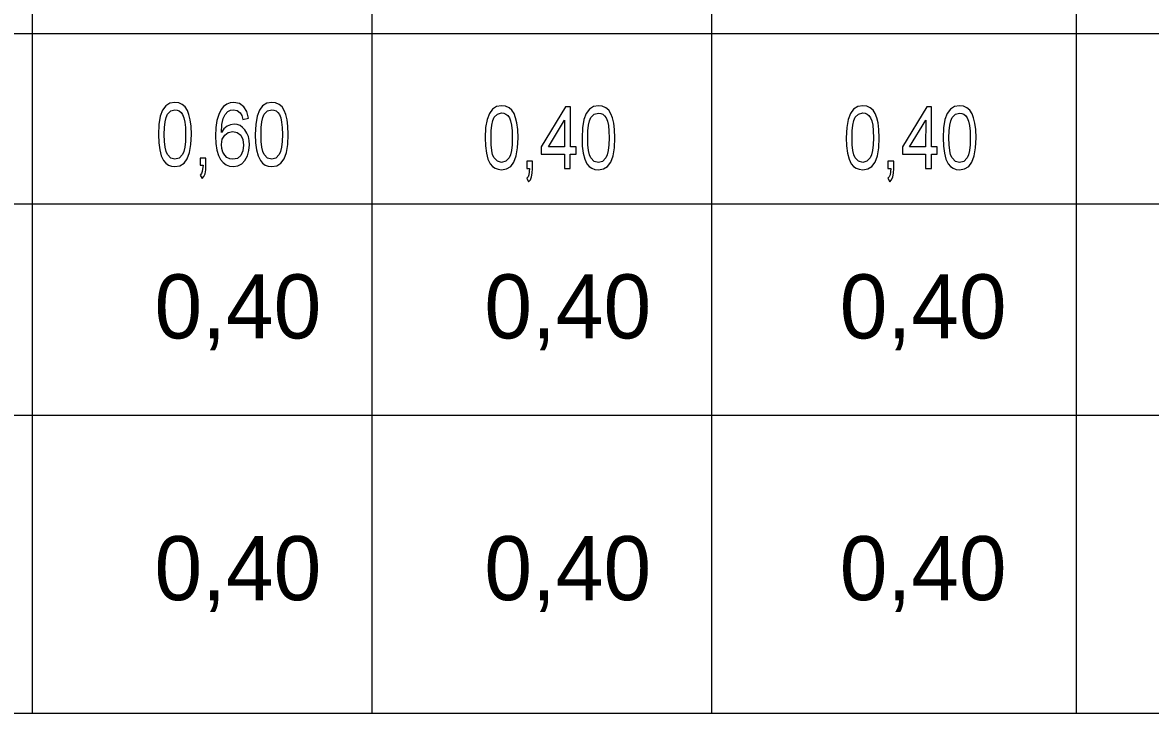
# Model space of a CAD drawing. Extents: x -480568.5 to -480543.1, y -1126945.4 to -1126930.6.
# Drawn here: x -480546.724 to -480545.02, y -1126939.812 to -1126938.768 of the extents above; entities that cross this region are included whole.
import ezdxf

# ---------------------------------------------------------------- set-up
doc = ezdxf.new("R2010")
doc.units = 0
doc.layers.add('detaily', color=7, linetype='Continuous')
doc.layers.add('EL1', color=7, linetype='Continuous')

msp = doc.modelspace()

# ---------------------------------------------------------------- linework, layer by layer
at = {"layer": 'detaily'}
msp.add_lwpolyline([(-480543.5956, -1126939.8124), (-480551.8459, -1126939.8124), (-480551.8459, -1126936.5789), (-480543.5956, -1126936.5789)], close=True, dxfattribs=at)
at = {"layer": 'EL1'}
for p, q in [((-480546.1966, -1126936.5789), (-480546.1966, -1126939.8121)), ((-480545.1324, -1126936.5789), (-480545.1324, -1126939.8121)), ((-480546.7093, -1126939.8121), (-480546.7093, -1126936.8775)), ((-480545.6831, -1126939.8121), (-480545.6831, -1126936.8775)), ((-480550.8351, -1126938.7844), (-480543.5956, -1126938.7844)), ((-480543.5956, -1126939.0426), (-480551.8459, -1126939.0426)), ((-480543.5956, -1126939.3618), (-480551.8459, -1126939.3618))]:
    msp.add_line(p, q, dxfattribs=at)
for points in [[(-480546.5189, -1126938.9373), (-480546.5184, -1126938.9498), (-480546.517, -1126938.9605), (-480546.5146, -1126938.9696), (-480546.5113, -1126938.9768), (-480546.5079, -1126938.9807), (-480546.5039, -1126938.9835), (-480546.4992, -1126938.9851), (-480546.494, -1126938.9857), (-480546.4864, -1126938.9844), (-480546.4802, -1126938.9805), (-480546.4754, -1126938.974), (-480546.4719, -1126938.9647), (-480546.4699, -1126938.9525), (-480546.4692, -1126938.9373), (-480546.4696, -1126938.9246), (-480546.4709, -1126938.9149), (-480546.4728, -1126938.9072), (-480546.4752, -1126938.9008), (-480546.4785, -1126938.8957), (-480546.4829, -1126938.8919), (-480546.4882, -1126938.8896), (-480546.494, -1126938.8888), (-480546.5016, -1126938.8901), (-480546.5078, -1126938.894), (-480546.5126, -1126938.9005), (-480546.5161, -1126938.9098), (-480546.5182, -1126938.922)], [(-480546.3829, -1126938.9126), (-480546.3852, -1126938.9027), (-480546.3899, -1126938.8952), (-480546.3965, -1126938.8904), (-480546.4048, -1126938.8888), (-480546.4106, -1126938.8895), (-480546.4158, -1126938.8916), (-480546.4204, -1126938.895), (-480546.4243, -1126938.8997), (-480546.4279, -1126938.9069), (-480546.4305, -1126938.916), (-480546.4321, -1126938.9269), (-480546.4326, -1126938.9397), (-480546.4321, -1126938.9511), (-480546.4307, -1126938.9608), (-480546.4284, -1126938.9688), (-480546.4251, -1126938.975), (-480546.421, -1126938.9797), (-480546.4165, -1126938.983), (-480546.4114, -1126938.985), (-480546.4057, -1126938.9857), (-480546.3991, -1126938.9846), (-480546.3932, -1126938.9816), (-480546.3883, -1126938.9765), (-480546.3846, -1126938.9697), (-480546.3822, -1126938.9616), (-480546.3814, -1126938.9528), (-480546.3818, -1126938.9463), (-480546.3831, -1126938.9404), (-480546.3852, -1126938.9351), (-480546.3882, -1126938.9304), (-480546.3918, -1126938.9266), (-480546.3957, -1126938.9239), (-480546.4, -1126938.9223), (-480546.4047, -1126938.9217), (-480546.4101, -1126938.9225), (-480546.4153, -1126938.9248), (-480546.4199, -1126938.9287), (-480546.4238, -1126938.9343), (-480546.423, -1126938.922), (-480546.421, -1126938.9133), (-480546.418, -1126938.9071), (-480546.4143, -1126938.9026), (-480546.4099, -1126938.9005), (-480546.4053, -1126938.8998), (-480546.3999, -1126938.901), (-480546.3954, -1126938.9047), (-480546.3932, -1126938.9087), (-480546.3916, -1126938.9144)], [(-480546.3726, -1126938.9373), (-480546.3721, -1126938.9498), (-480546.3707, -1126938.9605), (-480546.3684, -1126938.9696), (-480546.365, -1126938.9768), (-480546.3616, -1126938.9807), (-480546.3576, -1126938.9835), (-480546.353, -1126938.9851), (-480546.3477, -1126938.9857), (-480546.3401, -1126938.9844), (-480546.3339, -1126938.9805), (-480546.3291, -1126938.974), (-480546.3256, -1126938.9647), (-480546.3236, -1126938.9525), (-480546.3229, -1126938.9373), (-480546.3233, -1126938.9246), (-480546.3246, -1126938.9149), (-480546.3266, -1126938.9072), (-480546.329, -1126938.9008), (-480546.3322, -1126938.8957), (-480546.3366, -1126938.8919), (-480546.3419, -1126938.8896), (-480546.3477, -1126938.8888), (-480546.3553, -1126938.8901), (-480546.3615, -1126938.894), (-480546.3663, -1126938.9005), (-480546.3698, -1126938.9098), (-480546.3719, -1126938.922)], [(-480546.5101, -1126938.9373), (-480546.5098, -1126938.9269), (-480546.5089, -1126938.9183), (-480546.5074, -1126938.9115), (-480546.5054, -1126938.9064), (-480546.5003, -1126938.9015), (-480546.4941, -1126938.8998), (-480546.4907, -1126938.9003), (-480546.4876, -1126938.9017), (-480546.4848, -1126938.904), (-480546.4824, -1126938.9072), (-480546.4805, -1126938.9119), (-480546.4791, -1126938.9185), (-480546.4782, -1126938.9269), (-480546.4779, -1126938.9373), (-480546.4782, -1126938.948), (-480546.4791, -1126938.9566), (-480546.4806, -1126938.9632), (-480546.4826, -1126938.9677), (-480546.4878, -1126938.973), (-480546.494, -1126938.9747), (-480546.5003, -1126938.973), (-480546.5055, -1126938.9677), (-480546.5075, -1126938.9632), (-480546.509, -1126938.9566), (-480546.5098, -1126938.948)], [(-480546.3638, -1126938.9373), (-480546.3635, -1126938.9269), (-480546.3626, -1126938.9183), (-480546.3612, -1126938.9115), (-480546.3591, -1126938.9064), (-480546.3541, -1126938.9015), (-480546.3478, -1126938.8998), (-480546.3444, -1126938.9003), (-480546.3413, -1126938.9017), (-480546.3385, -1126938.904), (-480546.3361, -1126938.9072), (-480546.3342, -1126938.9119), (-480546.3328, -1126938.9185), (-480546.3319, -1126938.9269), (-480546.3317, -1126938.9373), (-480546.3319, -1126938.948), (-480546.3328, -1126938.9566), (-480546.3343, -1126938.9632), (-480546.3363, -1126938.9677), (-480546.3415, -1126938.973), (-480546.3477, -1126938.9747), (-480546.354, -1126938.973), (-480546.3592, -1126938.9677), (-480546.3612, -1126938.9632), (-480546.3627, -1126938.9566), (-480546.3635, -1126938.948)], [(-480546.0253, -1126938.9421), (-480546.0249, -1126938.9546), (-480546.0235, -1126938.9653), (-480546.0211, -1126938.9744), (-480546.0178, -1126938.9816), (-480546.0144, -1126938.9855), (-480546.0104, -1126938.9883), (-480546.0058, -1126938.9899), (-480546.0005, -1126938.9905), (-480545.9929, -1126938.9892), (-480545.9867, -1126938.9854), (-480545.9819, -1126938.9789), (-480545.9784, -1126938.9695), (-480545.9763, -1126938.9574), (-480545.9756, -1126938.9421), (-480545.976, -1126938.9295), (-480545.9773, -1126938.9197), (-480545.9793, -1126938.9121), (-480545.9817, -1126938.9056), (-480545.9849, -1126938.9005), (-480545.9893, -1126938.8968), (-480545.9946, -1126938.8944), (-480546.0004, -1126938.8937), (-480546.008, -1126938.8949), (-480546.0142, -1126938.8988), (-480546.019, -1126938.9053), (-480546.0225, -1126938.9146), (-480546.0246, -1126938.9268)], [(-480546.0165, -1126938.9421), (-480546.0163, -1126938.9317), (-480546.0154, -1126938.9231), (-480546.0139, -1126938.9163), (-480546.0118, -1126938.9112), (-480546.0067, -1126938.9063), (-480546.0005, -1126938.9046), (-480545.9971, -1126938.9051), (-480545.994, -1126938.9065), (-480545.9912, -1126938.9088), (-480545.9888, -1126938.9121), (-480545.9869, -1126938.9167), (-480545.9855, -1126938.9233), (-480545.9847, -1126938.9318), (-480545.9844, -1126938.9421), (-480545.9847, -1126938.9528), (-480545.9856, -1126938.9614), (-480545.9871, -1126938.968), (-480545.9891, -1126938.9725), (-480545.9943, -1126938.9778), (-480546.0005, -1126938.9795), (-480546.0068, -1126938.9778), (-480546.0119, -1126938.9725), (-480546.014, -1126938.968), (-480546.0154, -1126938.9614), (-480546.0163, -1126938.9528)], [(-480545.9055, -1126938.9888), (-480545.8967, -1126938.9888), (-480545.8967, -1126938.9669), (-480545.8879, -1126938.9669), (-480545.8879, -1126938.9559), (-480545.8966, -1126938.9559), (-480545.8966, -1126938.8956), (-480545.9039, -1126938.8956), (-480545.9405, -1126938.9559), (-480545.9405, -1126938.9668), (-480545.9054, -1126938.9669)], [(-480545.879, -1126938.9423), (-480545.8786, -1126938.9548), (-480545.8772, -1126938.9655), (-480545.8748, -1126938.9745), (-480545.8715, -1126938.9818), (-480545.8681, -1126938.9857), (-480545.8641, -1126938.9884), (-480545.8595, -1126938.9901), (-480545.8542, -1126938.9907), (-480545.8466, -1126938.9894), (-480545.8404, -1126938.9856), (-480545.8356, -1126938.9791), (-480545.8321, -1126938.9697), (-480545.8301, -1126938.9575), (-480545.8293, -1126938.9423), (-480545.8298, -1126938.9297), (-480545.831, -1126938.9199), (-480545.833, -1126938.9123), (-480545.8354, -1126938.9058), (-480545.8386, -1126938.9007), (-480545.843, -1126938.897), (-480545.8483, -1126938.8946), (-480545.8541, -1126938.8939), (-480545.8617, -1126938.8951), (-480545.8679, -1126938.8989), (-480545.8727, -1126938.9055), (-480545.8762, -1126938.9147), (-480545.8783, -1126938.927)], [(-480545.8703, -1126938.9422), (-480545.87, -1126938.9319), (-480545.8691, -1126938.9233), (-480545.8676, -1126938.9165), (-480545.8655, -1126938.9114), (-480545.8605, -1126938.9065), (-480545.8543, -1126938.9048), (-480545.8508, -1126938.9053), (-480545.8477, -1126938.9067), (-480545.8449, -1126938.909), (-480545.8425, -1126938.9122), (-480545.8406, -1126938.9169), (-480545.8392, -1126938.9235), (-480545.8384, -1126938.932), (-480545.8381, -1126938.9423), (-480545.8384, -1126938.953), (-480545.8393, -1126938.9616), (-480545.8408, -1126938.9682), (-480545.8428, -1126938.9727), (-480545.848, -1126938.978), (-480545.8542, -1126938.9797), (-480545.8605, -1126938.978), (-480545.8657, -1126938.9727), (-480545.8677, -1126938.9682), (-480545.8691, -1126938.9616), (-480545.87, -1126938.953)], [(-480545.4797, -1126938.9421), (-480545.4792, -1126938.9546), (-480545.4778, -1126938.9653), (-480545.4755, -1126938.9744), (-480545.4722, -1126938.9816), (-480545.4688, -1126938.9855), (-480545.4647, -1126938.9883), (-480545.4601, -1126938.9899), (-480545.4549, -1126938.9905), (-480545.4473, -1126938.9892), (-480545.441, -1126938.9854), (-480545.4362, -1126938.9789), (-480545.4328, -1126938.9695), (-480545.4307, -1126938.9574), (-480545.43, -1126938.9421), (-480545.4304, -1126938.9295), (-480545.4317, -1126938.9197), (-480545.4336, -1126938.9121), (-480545.436, -1126938.9056), (-480545.4392, -1126938.9005), (-480545.4436, -1126938.8968), (-480545.4489, -1126938.8944), (-480545.4548, -1126938.8937), (-480545.4624, -1126938.8949), (-480545.4686, -1126938.8988), (-480545.4734, -1126938.9053), (-480545.4768, -1126938.9146), (-480545.479, -1126938.9268)], [(-480545.4709, -1126938.9421), (-480545.4706, -1126938.9317), (-480545.4697, -1126938.9231), (-480545.4682, -1126938.9163), (-480545.4661, -1126938.9112), (-480545.4611, -1126938.9063), (-480545.4549, -1126938.9046), (-480545.4514, -1126938.9051), (-480545.4483, -1126938.9065), (-480545.4456, -1126938.9088), (-480545.4432, -1126938.9121), (-480545.4412, -1126938.9167), (-480545.4398, -1126938.9233), (-480545.439, -1126938.9318), (-480545.4387, -1126938.9421), (-480545.439, -1126938.9528), (-480545.4399, -1126938.9614), (-480545.4414, -1126938.968), (-480545.4434, -1126938.9725), (-480545.4486, -1126938.9778), (-480545.4549, -1126938.9795), (-480545.4611, -1126938.9778), (-480545.4663, -1126938.9725), (-480545.4683, -1126938.968), (-480545.4698, -1126938.9614), (-480545.4706, -1126938.9528)], [(-480545.3598, -1126938.9888), (-480545.351, -1126938.9888), (-480545.351, -1126938.9669), (-480545.3422, -1126938.9669), (-480545.3422, -1126938.9559), (-480545.351, -1126938.9559), (-480545.3509, -1126938.8956), (-480545.3582, -1126938.8956), (-480545.3948, -1126938.9559), (-480545.3949, -1126938.9668), (-480545.3598, -1126938.9669)], [(-480545.3334, -1126938.9423), (-480545.3329, -1126938.9548), (-480545.3315, -1126938.9655), (-480545.3292, -1126938.9745), (-480545.3259, -1126938.9818), (-480545.3225, -1126938.9857), (-480545.3184, -1126938.9884), (-480545.3138, -1126938.9901), (-480545.3086, -1126938.9907), (-480545.301, -1126938.9894), (-480545.2947, -1126938.9856), (-480545.2899, -1126938.9791), (-480545.2865, -1126938.9697), (-480545.2844, -1126938.9575), (-480545.2837, -1126938.9423), (-480545.2841, -1126938.9297), (-480545.2854, -1126938.9199), (-480545.2873, -1126938.9123), (-480545.2897, -1126938.9058), (-480545.293, -1126938.9007), (-480545.2974, -1126938.897), (-480545.3026, -1126938.8946), (-480545.3085, -1126938.8939), (-480545.3161, -1126938.8951), (-480545.3223, -1126938.8989), (-480545.3271, -1126938.9055), (-480545.3306, -1126938.9147), (-480545.3327, -1126938.927)], [(-480545.3246, -1126938.9422), (-480545.3243, -1126938.9319), (-480545.3234, -1126938.9233), (-480545.3219, -1126938.9165), (-480545.3198, -1126938.9114), (-480545.3148, -1126938.9065), (-480545.3086, -1126938.9048), (-480545.3052, -1126938.9053), (-480545.302, -1126938.9067), (-480545.2993, -1126938.909), (-480545.2969, -1126938.9122), (-480545.295, -1126938.9169), (-480545.2935, -1126938.9235), (-480545.2927, -1126938.932), (-480545.2925, -1126938.9423), (-480545.2928, -1126938.953), (-480545.2936, -1126938.9616), (-480545.2951, -1126938.9682), (-480545.2971, -1126938.9727), (-480545.3023, -1126938.978), (-480545.3086, -1126938.9797), (-480545.3149, -1126938.978), (-480545.32, -1126938.9727), (-480545.3221, -1126938.9682), (-480545.3235, -1126938.9616), (-480545.3243, -1126938.953)], [(-480545.9054, -1126938.9559), (-480545.9298, -1126938.9559), (-480545.9054, -1126938.9156)], [(-480545.3598, -1126938.9559), (-480545.3842, -1126938.9559), (-480545.3597, -1126938.9156)], [(-480546.4238, -1126938.9526), (-480546.4226, -1126938.9445), (-480546.4188, -1126938.9382), (-480546.4134, -1126938.9341), (-480546.4068, -1126938.9327), (-480546.3998, -1126938.9341), (-480546.3945, -1126938.9382), (-480546.3913, -1126938.9447), (-480546.3902, -1126938.9532), (-480546.3913, -1126938.9621), (-480546.3946, -1126938.9689), (-480546.3997, -1126938.9733), (-480546.4064, -1126938.9747), (-480546.4113, -1126938.974), (-480546.4154, -1126938.9719), (-480546.4188, -1126938.9685), (-480546.4215, -1126938.9638), (-480546.4232, -1126938.9583)], [(-480546.456, -1126938.9838), (-480546.4516, -1126938.9838), (-480546.4527, -1126938.9934), (-480546.4541, -1126938.9963), (-480546.456, -1126938.9985), (-480546.453, -1126939.0039), (-480546.4504, -1126939.0008), (-480546.4486, -1126938.9965), (-480546.4475, -1126938.9909), (-480546.4472, -1126938.9838), (-480546.4472, -1126938.9729), (-480546.456, -1126938.9729)], [(-480545.9625, -1126938.9887), (-480545.9581, -1126938.9887), (-480545.9593, -1126938.9983), (-480545.9606, -1126939.0012), (-480545.9625, -1126939.0033), (-480545.9596, -1126939.0088), (-480545.957, -1126939.0056), (-480545.9551, -1126939.0014), (-480545.9541, -1126938.9958), (-480545.9537, -1126938.9887), (-480545.9537, -1126938.9778), (-480545.9625, -1126938.9778)], [(-480545.4168, -1126938.9887), (-480545.4125, -1126938.9887), (-480545.4136, -1126938.9983), (-480545.4149, -1126939.0012), (-480545.4168, -1126939.0033), (-480545.4139, -1126939.0088), (-480545.4113, -1126939.0056), (-480545.4095, -1126939.0014), (-480545.4084, -1126938.9958), (-480545.408, -1126938.9887), (-480545.408, -1126938.9778), (-480545.4168, -1126938.9778)]]:
    msp.add_lwpolyline(points, close=True, dxfattribs=at)

# ---------------------------------------------------------------- texts
for rotation, p in [(360, (-480546.5249, -1126939.2455)), (360, (-480546.0265, -1126939.2455)), (360, (-480545.4896, -1126939.2455)), (360, (-480546.5249, -1126939.6412)), (0, (-480546.0265, -1126939.6412)), (360, (-480545.4896, -1126939.6412))]:
    msp.add_text('0,40', height=0.09683, rotation=rotation, dxfattribs=at).set_placement(p)

doc.saveas('drawing.dxf')
